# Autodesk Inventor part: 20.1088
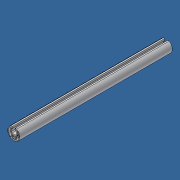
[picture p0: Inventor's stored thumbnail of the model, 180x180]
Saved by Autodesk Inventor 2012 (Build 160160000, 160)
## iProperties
Created: 2014-04
Part Number: 20.1088
Material: Aluminum-6061
Description: L = TRAVEL + 3.74", T1E M8
Document SubType Name: Modeling
Designer: Admin
Stock Number: HANDLE PROFILE 32
Density: 2.71 g/cm^3
Vendor: F
FINISH: CLEAR ANODIZED
Author: Admin
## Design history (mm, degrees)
sketch "Sketch1"
  geometry: L1 (4.596, -3.182)-(3.263, -1.849); L2 (3.182, -4.596)-(4.596, -3.182); L3 (1.849, -3.263)-(3.182, -4.596); L4 (-3.182, -4.596)-(-1.849, -3.263); L5 (-4.596, -3.182)-(-3.182, -4.596); L6 (-3.263, -1.849)-(-4.596, -3.182); L7 (-4.596, 3.182)-(-3.263, 1.849); L8 (-3.182, 4.596)-(-4.596, 3.182); L9 (-1.849, 3.263)-(-3.182, 4.596); L10 (3.182, 4.596)-(1.849, 3.263); L11 (4.596, 3.182)-(3.182, 4.596); L12 (3.263, 1.849)-(4.596, 3.182); L13 (6.418, 2.685)-(5.767, -0.255); L14 (8.8, 8.672)-(6.058, 5.93); L15 (8.8, 17.042)-(8.8, 8.672); L16 (-6.058, 5.93)-(-8.8, 8.672); L17 (-5.767, -0.255)-(-6.418, 2.685); L18 (-8.8, 8.672)-(-8.8, 17.042); L19 (4.1, 22.5)-(7.746, 22.5); L20 (4.1, 18)-(4.1, 22.5); L21 (6.8, 18)-(4.1, 18); L22 (6.8, 9.5)-(6.8, 18); L23 (4.5, 7.2)-(6.8, 9.5); L24 (-4.5, 7.2)-(4.5, 7.2); L25 (-6.8, 9.5)-(-4.5, 7.2); L26 (-6.8, 18)-(-6.8, 9.5); L27 (-4.1, 18)-(-6.8, 18); L28 (-4.1, 22.5)-(-4.1, 18); L29 (-7.746, 22.5)-(-4.1, 22.5); A1 r 3.75 centre (0, 0) between (-1.849, -3.263) and (1.849, -3.263); A2 r 3.75 centre (0, 0) between (-3.263, 1.849) and (-3.263, -1.849); A3 r 3.75 centre (0, 0) between (1.849, 3.263) and (-1.849, 3.263); A4 r 3.75 centre (0, 0) between (3.263, -1.849) and (3.263, 1.849); A5 r 1 centre (9.8, 17.042) between (10.554, 17.699) and (8.8, 17.042); A6 r 14 centre (0, 8.5) between (9.006, -2.219) and (10.554, 17.699); A7 r 2 centre (7.719, -0.688) between (5.767, -0.255) and (9.006, -2.219); A8 r 2.3 centre (4.172, 3.182) between (6.418, 2.685) and (5.979, 4.604); A9 r 1 centre (6.765, 5.223) between (6.058, 5.93) and (5.979, 4.604); A10 r 1 centre (-6.765, 5.223) between (-5.979, 4.604) and (-6.058, 5.93); A11 r 2.3 centre (-4.172, 3.182) between (-5.979, 4.604) and (-6.418, 2.685); A12 r 2 centre (-7.719, -0.688) between (-9.006, -2.219) and (-5.767, -0.255); A13 r 14 centre (0, 8.5) between (-10.554, 17.699) and (-9.006, -2.219); A14 r 1 centre (-9.8, 17.042) between (-8.8, 17.042) and (-10.554, 17.699); A15 r 16 centre (0, 8.5) between (-7.746, 22.5) and (7.746, 22.5); 1 further point
  constraints: 58 end point, 30 point on circle, 15 centre point
extrude "Extrusion1" new body sketch "Sketch1" distance "d0" = 399.8; taper "d1" = 0 deg
thread "Thread1" dims "d2" = 25.4, "d3" = 0
thread "Thread2" dims "d4" = 25.4, "d5" = 0
thread "Thread3" dims "d6" = 25.4, "d7" = 0
thread "Thread4" dims "d8" = 25.4, "d9" = 0
body "Solid1"
